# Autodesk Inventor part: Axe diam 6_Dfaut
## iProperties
Created: 2006-03
Part Number: Axe diam 6_Dfaut
Document SubType Name: Modeling
Designer: Flavien MARTY
Author: Flavien MARTY
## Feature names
1. Base1
